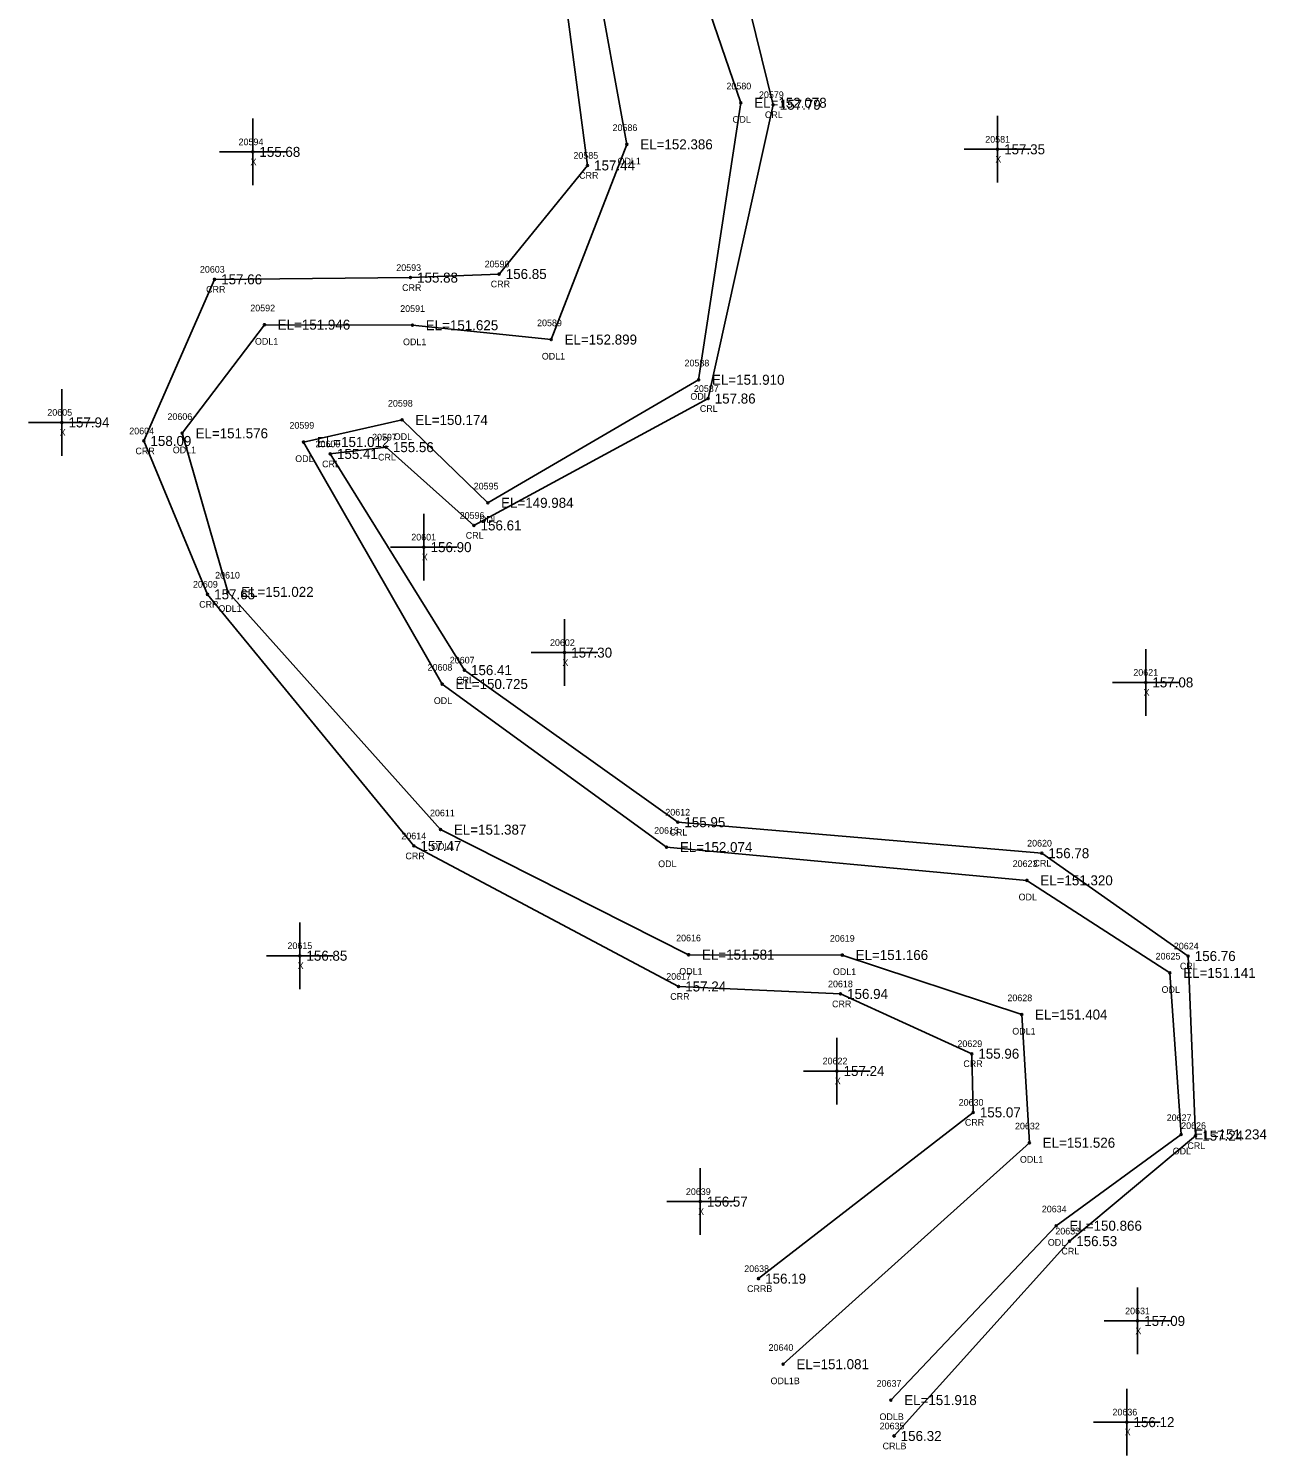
# Model space of a CAD drawing. Extents: x 2279528 to 2280976, y 1061373 to 1062235.
# Drawn here: x 2280203.9 to 2280389.7, y 1061385 to 1061599.1 of the extents above; entities that cross this region are included whole.
import ezdxf

# ---------------------------------------------------------------- set-up
doc = ezdxf.new("R2010")
doc.units = 0
for name, color, linetype in [('RD_EX_H2O', 7, 'Continuous'), ('RD_EX_H2O_txCode', 7, 'Continuous'), ('RD_EX_Misc', 7, 'Continuous'), ('RD_EX_Misc_txCode', 7, 'Continuous'), ('RD_EX_TX_H2O_ELEV', 7, 'Continuous'), ('RD_EX_TX_Misc_ELEV', 7, 'Continuous'), ('RD_SMD_Locator', 7, 'Continuous')]:
    doc.layers.add(name, color=color, linetype=linetype)

msp = doc.modelspace()

# ---------------------------------------------------------------- linework, layer by layer
at = {"layer": 'RD_EX_H2O'}
for points in [[(2280243.56, 1061789.13), (2280258.67, 1061797.27), (2280267.66, 1061787.82), (2280287.8, 1061761.36), (2280315.22, 1061731.8), (2280327.48, 1061683.93), (2280307.76, 1061678.04), (2280294.04, 1061661.65), (2280295.74, 1061631.81), (2280310.81, 1061587.94), (2280304.48, 1061546.39), (2280272.84, 1061527.93), (2280259.98, 1061540.36), (2280245.21, 1061537.05), (2280265.99, 1061500.75), (2280299.66, 1061476.28), (2280353.73, 1061471.3), (2280375.17, 1061457.42), (2280376.85, 1061433.19), (2280358.1, 1061419.49), (2280333.32, 1061393.34)], [(2280269.9, 1061794.49), (2280270.02, 1061790.74), (2280293.77, 1061763.48), (2280320.49, 1061735.05), (2280335.4, 1061680.01), (2280309.48, 1061674.63), (2280300.03, 1061660.41), (2280304.47, 1061633.12), (2280315.65, 1061587.64), (2280305.89, 1061543.57), (2280270.77, 1061524.54), (2280257.61, 1061536.28), (2280249.22, 1061535.26), (2280269.33, 1061502.83), (2280301.34, 1061480.02), (2280355.94, 1061475.37), (2280377.91, 1061459.94), (2280379.03, 1061433), (2280360.13, 1061417.18), (2280333.79, 1061387.95)], [(2280219.49, 1061771.9), (2280219.45, 1061768.68), (2280220.02, 1061767.07), (2280223.01, 1061764.94), (2280232.42, 1061752.34), (2280266.07, 1061747.74), (2280284.73, 1061725.48), (2280294.86, 1061698.39), (2280278.35, 1061688.54), (2280267.33, 1061659.35), (2280270.69, 1061629.09), (2280284.25, 1061605.42), (2280287.8, 1061578.54), (2280274.54, 1061562.25), (2280261.24, 1061561.71), (2280231.85, 1061561.45), (2280221.24, 1061537.21), (2280230.8, 1061514.2), (2280261.74, 1061476.46), (2280301.47, 1061455.38), (2280325.75, 1061454.26), (2280345.44, 1061445.29), (2280345.67, 1061436.49), (2280313.46, 1061411.55)], [(2280269.44, 1061752.22), (2280294.62, 1061728.95), (2280307.92, 1061693.91), (2280286.99, 1061684.11), (2280274.68, 1061657.45), (2280275.58, 1061630.25), (2280288.86, 1061608.44), (2280293.72, 1061581.7), (2280282.36, 1061552.42), (2280261.54, 1061554.57), (2280239.33, 1061554.65), (2280227, 1061538.36), (2280233.84, 1061514.57), (2280265.76, 1061478.91), (2280302.98, 1061460.15), (2280326.03, 1061460.1), (2280352.94, 1061451.17), (2280354.09, 1061431.94), (2280317.15, 1061398.72)]]:
    msp.add_lwpolyline(points, dxfattribs=at)
at = {"layer": 'RD_EX_Misc'}
for p, q in [((2280237.58, 1061575.57), (2280237.58, 1061585.57)), ((2280349.31, 1061575.96), (2280349.31, 1061585.96)), ((2280232.58, 1061580.57), (2280242.58, 1061580.57)), ((2280344.31, 1061580.96), (2280354.31, 1061580.96)), ((2280208.95, 1061534.99), (2280208.95, 1061544.99)), ((2280203.95, 1061539.99), (2280213.95, 1061539.99)), ((2280263.27, 1061516.28), (2280263.27, 1061526.28)), ((2280258.27, 1061521.28), (2280268.27, 1061521.28)), ((2280284.36, 1061500.46), (2280284.36, 1061510.46)), ((2280371.55, 1061495.99), (2280371.55, 1061505.99)), ((2280279.36, 1061505.46), (2280289.36, 1061505.46)), ((2280366.55, 1061500.99), (2280376.55, 1061500.99)), ((2280244.64, 1061454.99), (2280244.64, 1061464.99)), ((2280239.64, 1061459.99), (2280249.64, 1061459.99)), ((2280325.22, 1061437.7), (2280325.22, 1061447.7)), ((2280320.22, 1061442.7), (2280330.22, 1061442.7)), ((2280304.71, 1061418.11), (2280304.71, 1061428.11)), ((2280299.71, 1061423.11), (2280309.71, 1061423.11)), ((2280370.32, 1061400.21), (2280370.32, 1061410.21)), ((2280365.32, 1061405.21), (2280375.32, 1061405.21)), ((2280368.72, 1061385.03), (2280368.72, 1061395.03)), ((2280363.72, 1061390.03), (2280373.72, 1061390.03))]:
    msp.add_line(p, q, dxfattribs=at)
at = {"layer": 'RD_SMD_Locator'}
for centre in [(2280310.81, 1061587.94), (2280315.65, 1061587.64), (2280237.58, 1061580.57), (2280293.72, 1061581.7), (2280349.31, 1061580.96), (2280287.8, 1061578.54), (2280231.85, 1061561.45), (2280261.24, 1061561.71), (2280274.54, 1061562.25), (2280239.33, 1061554.65), (2280261.54, 1061554.57), (2280282.36, 1061552.42), (2280304.48, 1061546.39), (2280305.89, 1061543.57), (2280208.95, 1061539.99), (2280259.98, 1061540.36), (2280227, 1061538.36), (2280221.24, 1061537.21), (2280245.21, 1061537.05), (2280257.61, 1061536.28), (2280249.22, 1061535.26), (2280272.84, 1061527.93), (2280270.77, 1061524.54), (2280263.27, 1061521.28), (2280230.8, 1061514.2), (2280233.84, 1061514.57), (2280284.36, 1061505.46), (2280269.33, 1061502.83), (2280265.99, 1061500.75), (2280371.55, 1061500.99), (2280301.34, 1061480.02), (2280265.76, 1061478.91), (2280261.74, 1061476.46), (2280299.66, 1061476.28), (2280355.94, 1061475.37), (2280353.73, 1061471.3), (2280244.64, 1061459.99), (2280302.98, 1061460.15), (2280326.03, 1061460.1), (2280377.91, 1061459.94), (2280375.17, 1061457.42), (2280301.47, 1061455.38), (2280325.75, 1061454.26), (2280352.94, 1061451.17), (2280345.44, 1061445.29), (2280325.22, 1061442.7), (2280345.67, 1061436.49), (2280376.85, 1061433.19), (2280379.03, 1061433), (2280354.09, 1061431.94), (2280304.71, 1061423.11), (2280358.1, 1061419.49), (2280360.13, 1061417.18), (2280313.46, 1061411.55), (2280370.32, 1061405.21), (2280317.15, 1061398.72), (2280333.32, 1061393.34), (2280368.72, 1061390.03), (2280333.79, 1061387.95)]:
    msp.add_circle(centre, 0.15, dxfattribs=at)

# ---------------------------------------------------------------- texts
at = {"layer": 'RD_EX_H2O_txCode'}
for s, p in [('20580', (2280308.65, 1061589.94)), ('20579', (2280313.53, 1061588.64)), ('ODL', (2280309.56, 1061584.94)), ('CRL', (2280314.42, 1061585.64)), ('20586', (2280291.57, 1061583.7)), ('20585', (2280285.69, 1061579.54)), ('ODL1', (2280292.31, 1061578.7)), ('CRR', (2280286.55, 1061576.54)), ('20603', (2280229.66, 1061562.45)), ('20593', (2280259.12, 1061562.71)), ('20590', (2280272.38, 1061563.25)), ('CRR', (2280273.29, 1061560.25)), ('CRR', (2280230.59, 1061559.45)), ('CRR', (2280259.99, 1061559.71)), ('20592', (2280237.22, 1061556.65)), ('20591', (2280259.71, 1061556.57)), ('20589', (2280280.24, 1061554.42)), ('ODL1', (2280237.92, 1061551.65)), ('ODL1', (2280260.13, 1061551.57)), ('ODL1', (2280280.95, 1061549.42)), ('20588', (2280302.36, 1061548.39)), ('ODL', (2280303.24, 1061543.39)), ('20587', (2280303.77, 1061544.57)), ('20598', (2280257.87, 1061542.36)), ('CRL', (2280304.66, 1061541.57)), ('20606', (2280224.79, 1061540.36)), ('20599', (2280243.09, 1061539.05)), ('20604', (2280219.06, 1061538.21)), ('20597', (2280255.49, 1061537.28)), ('ODL', (2280258.74, 1061537.36)), ('CRR', (2280219.99, 1061535.21)), ('ODL1', (2280225.59, 1061535.36)), ('20600', (2280247, 1061536.26)), ('ODL', (2280243.96, 1061534.05)), ('CRL', (2280247.99, 1061533.26)), ('CRL', (2280256.38, 1061534.28)), ('20595', (2280270.73, 1061529.93)), ('20596', (2280268.63, 1061525.54)), ('ODL', (2280271.6, 1061524.93)), ('CRL', (2280269.54, 1061522.54)), ('20610', (2280231.94, 1061516.57)), ('20609', (2280228.62, 1061515.2)), ('CRR', (2280229.55, 1061512.2)), ('ODL1', (2280232.43, 1061511.57)), ('20608', (2280263.81, 1061502.75)), ('20607', (2280267.15, 1061503.83)), ('CRL', (2280268.1, 1061500.83)), ('ODL', (2280264.75, 1061497.75)), ('20611', (2280264.18, 1061480.91)), ('20612', (2280299.48, 1061481.02)), ('20614', (2280259.88, 1061477.46)), ('20613', (2280297.8, 1061478.28)), ('CRL', (2280300.11, 1061478.02)), ('ODL1', (2280264.35, 1061475.91)), ('20620', (2280353.76, 1061476.37)), ('CRR', (2280260.49, 1061474.46)), ('ODL', (2280298.41, 1061473.28)), ('20623', (2280351.59, 1061473.3)), ('CRL', (2280354.71, 1061473.37)), ('ODL', (2280352.48, 1061468.3)), ('20616', (2280301.1, 1061462.15)), ('20619', (2280324.17, 1061462.1)), ('20624', (2280375.77, 1061460.94)), ('20625', (2280373.03, 1061459.42)), ('CRL', (2280376.68, 1061457.94)), ('20617', (2280299.62, 1061456.38)), ('ODL1', (2280301.57, 1061457.15)), ('ODL1', (2280324.62, 1061457.1)), ('CRR', (2280300.22, 1061453.38)), ('20618', (2280323.89, 1061455.26)), ('ODL', (2280373.93, 1061454.42)), ('CRR', (2280324.49, 1061452.26)), ('20628', (2280350.8, 1061453.17)), ('ODL1', (2280351.53, 1061448.17)), ('20629', (2280343.3, 1061446.29)), ('CRR', (2280344.19, 1061443.29)), ('20630', (2280343.49, 1061437.49)), ('CRR', (2280344.42, 1061434.49)), ('20627', (2280374.7, 1061435.19)), ('20626', (2280376.87, 1061434)), ('20632', (2280351.94, 1061433.94)), ('ODL', (2280375.6, 1061430.19)), ('CRL', (2280377.8, 1061431)), ('ODL1', (2280352.68, 1061428.94)), ('20634', (2280355.96, 1061421.49)), ('20633', (2280357.99, 1061418.18)), ('ODL', (2280356.86, 1061416.49)), ('CRL', (2280358.9, 1061415.18)), ('20638', (2280311.32, 1061412.55)), ('CRRB', (2280311.74, 1061409.55)), ('20640', (2280314.97, 1061400.72)), ('ODL1B', (2280315.27, 1061395.72)), ('20637', (2280331.18, 1061395.34)), ('ODLB', (2280331.61, 1061390.34)), ('20635', (2280331.64, 1061388.95)), ('CRLB', (2280332.08, 1061385.95))]:
    msp.add_text(s, height=1, dxfattribs=at).set_placement(p)
at = {"layer": 'RD_EX_Misc_txCode'}
for s, p in [('20581', (2280347.48, 1061581.96)), ('20594', (2280235.46, 1061581.57)), ('X', (2280237.26, 1061578.57)), ('X', (2280348.99, 1061578.96)), ('20605', (2280206.77, 1061540.99)), ('X', (2280208.63, 1061537.99)), ('20601', (2280261.37, 1061522.28)), ('X', (2280262.95, 1061519.28)), ('20602', (2280282.18, 1061506.46)), ('X', (2280284.04, 1061503.46)), ('20621', (2280369.69, 1061501.99)), ('X', (2280371.23, 1061498.99)), ('20615', (2280242.79, 1061460.99)), ('X', (2280244.33, 1061457.99)), ('20622', (2280323.08, 1061443.7)), ('X', (2280324.91, 1061440.7)), ('20639', (2280302.57, 1061424.11)), ('X', (2280304.4, 1061421.11)), ('20631', (2280368.46, 1061406.21)), ('X', (2280370, 1061403.21)), ('20636', (2280366.56, 1061391.03)), ('X', (2280368.41, 1061388.03))]:
    msp.add_text(s, height=1, dxfattribs=at).set_placement(p)
at = {"layer": 'RD_EX_TX_H2O_ELEV'}
for s, p in [('EL=152.078', (2280312.81, 1061587.19)), ('157.79', (2280316.65, 1061586.89)), ('EL=152.386', (2280295.72, 1061580.95)), ('157.44', (2280288.8, 1061577.79)), ('157.66', (2280232.85, 1061560.7)), ('155.88', (2280262.24, 1061560.96)), ('156.85', (2280275.54, 1061561.5)), ('EL=151.946', (2280241.33, 1061553.9)), ('EL=151.625', (2280263.54, 1061553.82)), ('EL=152.899', (2280284.36, 1061551.67)), ('EL=151.910', (2280306.48, 1061545.64)), ('157.86', (2280306.89, 1061542.82)), ('EL=150.174', (2280261.98, 1061539.61)), ('158.09', (2280222.24, 1061536.46)), ('EL=151.576', (2280229, 1061537.61)), ('EL=151.012', (2280247.21, 1061536.3)), ('155.41', (2280250.22, 1061534.51)), ('155.56', (2280258.61, 1061535.53)), ('EL=149.984', (2280274.84, 1061527.18)), ('156.61', (2280271.77, 1061523.79)), ('157.65', (2280231.8, 1061513.45)), ('EL=151.022', (2280235.84, 1061513.82)), ('156.41', (2280270.33, 1061502.08)), ('EL=150.725', (2280267.99, 1061500)), ('155.95', (2280302.34, 1061479.27)), ('EL=151.387', (2280267.76, 1061478.16)), ('157.47', (2280262.74, 1061475.71)), ('EL=152.074', (2280301.66, 1061475.53)), ('156.78', (2280356.94, 1061474.62)), ('EL=151.320', (2280355.73, 1061470.55)), ('EL=151.581', (2280304.98, 1061459.4)), ('EL=151.166', (2280328.03, 1061459.35)), ('156.76', (2280378.91, 1061459.19)), ('EL=151.141', (2280377.17, 1061456.67)), ('157.24', (2280302.47, 1061454.63)), ('156.94', (2280326.75, 1061453.51)), ('EL=151.404', (2280354.94, 1061450.42)), ('155.96', (2280346.44, 1061444.54)), ('155.07', (2280346.67, 1061435.74)), ('EL=151.234', (2280378.85, 1061432.44)), ('157.24', (2280380.03, 1061432.25)), ('EL=151.526', (2280356.09, 1061431.19)), ('EL=150.866', (2280360.1, 1061418.74)), ('156.53', (2280361.13, 1061416.43)), ('156.19', (2280314.46, 1061410.8)), ('EL=151.081', (2280319.15, 1061397.97)), ('EL=151.918', (2280335.32, 1061392.59)), ('156.32', (2280334.79, 1061387.2))]:
    msp.add_text(s, height=1.5, dxfattribs=at).set_placement(p)
at = {"layer": 'RD_EX_TX_Misc_ELEV'}
for s, p in [('155.68', (2280238.58, 1061579.82)), ('157.35', (2280350.31, 1061580.21)), ('157.94', (2280209.95, 1061539.24)), ('156.90', (2280264.27, 1061520.53)), ('157.30', (2280285.36, 1061504.71)), ('157.08', (2280372.55, 1061500.24)), ('156.85', (2280245.64, 1061459.24)), ('157.24', (2280326.22, 1061441.95)), ('156.57', (2280305.71, 1061422.36)), ('157.09', (2280371.32, 1061404.46)), ('156.12', (2280369.72, 1061389.28))]:
    msp.add_text(s, height=1.5, dxfattribs=at).set_placement(p)

doc.saveas('drawing.dxf')
